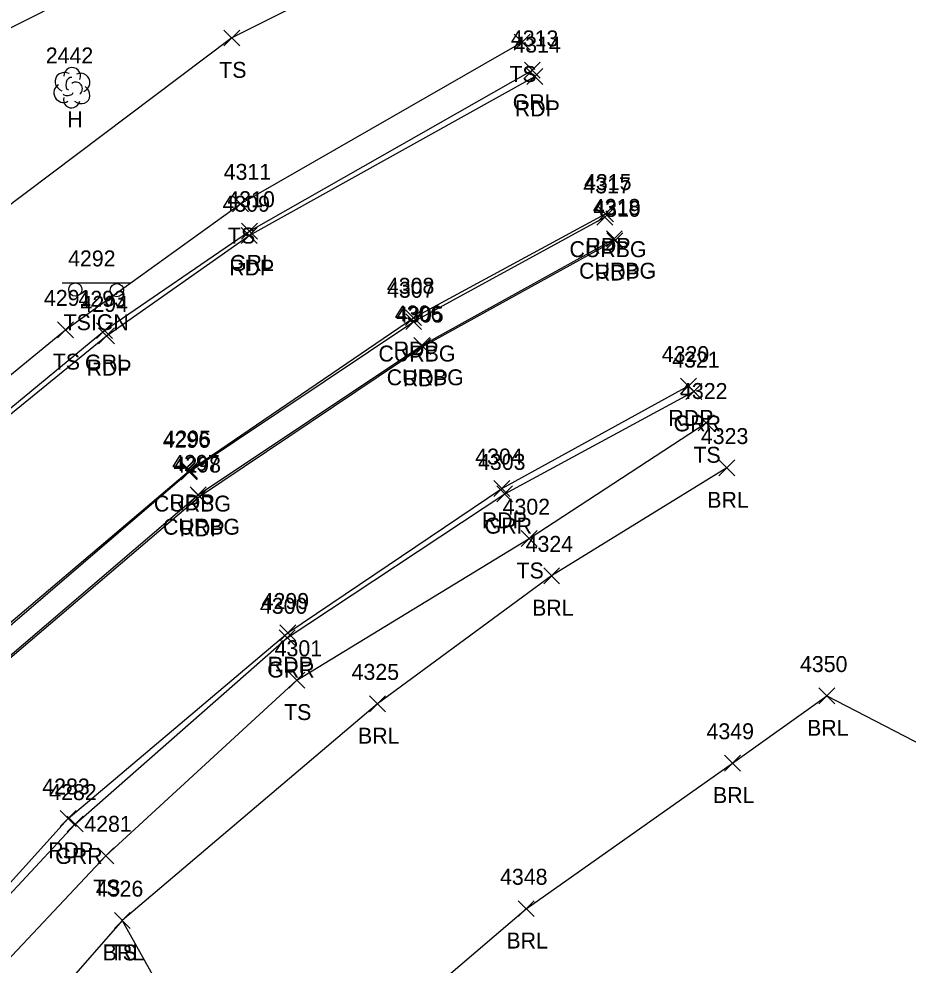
# Model space of a CAD drawing. Extents: x 1505656 to 1508446, y 700805 to 703031.
# Drawn here: x 1506963.6 to 1507075.1, y 702077.2 to 702195.8 of the extents above; entities that cross this region are included whole.
import ezdxf

# ---------------------------------------------------------------- set-up
doc = ezdxf.new("R2010")
doc.units = 0
for name, color, linetype in [('L_A', 7, 'Continuous'), ('L_I', 7, 'Continuous'), ('L_TIC', 7, 'Continuous'), ('LABL', 7, 'Continuous'), ('LELB', 7, 'Continuous'), ('LFNC', 7, 'Continuous'), ('LTD', 7, 'Continuous'), ('P_A', 7, 'Continuous'), ('P_I', 7, 'Continuous'), ('P_TIC', 7, 'Continuous'), ('PET', 7, 'Continuous'), ('R_A', 7, 'Continuous'), ('R_I', 7, 'Continuous'), ('R_TIC', 7, 'Continuous'), ('RC', 7, 'Continuous'), ('RGR', 7, 'Continuous'), ('S_A', 7, 'Continuous'), ('S_I', 7, 'Continuous'), ('SSGN', 7, 'Continuous')]:
    doc.layers.add(name, color=color, linetype=linetype)

msp = doc.modelspace()

# ---------------------------------------------------------------- linework, layer by layer
at = {"layer": 'L_TIC'}
for points in [[(1506989.29, 702192.44), (1506991.29, 702194.44)], [(1506991.29, 702192.44), (1506989.29, 702194.44)], [(1507025.67, 702191.92), (1507027.67, 702193.92)], [(1507027.67, 702191.92), (1507025.67, 702193.92)], [(1506990.38, 702171.65), (1506992.38, 702173.65)], [(1506992.38, 702171.65), (1506990.38, 702173.65)], [(1506968.42, 702155.84), (1506970.42, 702157.84)], [(1506970.42, 702155.84), (1506968.42, 702157.84)], [(1507048.74, 702144.16), (1507050.74, 702146.16)], [(1507050.74, 702144.16), (1507048.74, 702146.16)], [(1507051.35, 702138.51), (1507053.35, 702140.51)], [(1507053.35, 702138.51), (1507051.35, 702140.51)], [(1507026.57, 702129.65), (1507028.57, 702131.65)], [(1507028.57, 702129.65), (1507026.57, 702131.65)], [(1507029.38, 702124.98), (1507031.38, 702126.98)], [(1507031.38, 702124.98), (1507029.38, 702126.98)], [(1506997.42, 702111.89), (1506999.42, 702113.89)], [(1506999.42, 702111.89), (1506997.42, 702113.89)], [(1507063.87, 702109.91), (1507065.87, 702111.91)], [(1507065.87, 702109.91), (1507063.87, 702111.91)], [(1507007.56, 702108.93), (1507009.56, 702110.93)], [(1507009.56, 702108.93), (1507007.56, 702110.93)], [(1507052.07, 702101.48), (1507054.07, 702103.48)], [(1507054.07, 702101.48), (1507052.07, 702103.48)], [(1506973.48, 702089.87), (1506975.48, 702091.87)], [(1506975.48, 702089.87), (1506973.48, 702091.87)], [(1507026.17, 702083.23), (1507028.17, 702085.23)], [(1507028.17, 702083.23), (1507026.17, 702085.23)], [(1506975.55, 702081.74), (1506977.55, 702083.74)], [(1506977.55, 702081.74), (1506975.55, 702083.74)], [(1506975.55, 702081.74), (1506977.55, 702083.74)], [(1506977.55, 702081.74), (1506975.55, 702083.74)]]:
    msp.add_lwpolyline(points, dxfattribs=at)
at = {"layer": 'LABL'}
msp.add_lwpolyline([(1507052.35, 702139.51), (1507030.38, 702125.98), (1507008.56, 702109.93), (1506976.55, 702082.74), (1506991.06, 702056.7), (1507008.55, 702068.3), (1507027.17, 702084.23), (1507053.07, 702102.48), (1507064.87, 702110.91), (1507096.41, 702094.62), (1507120.62, 702079.29), (1507138.79, 702060.47), (1507154.26, 702038.91)], dxfattribs=at)
at = {"layer": 'LELB'}
for points in [[(1507023.62, 702210.14), (1506990.29, 702193.44), (1506954.68, 702166.67), (1506927.59, 702146.34), (1506906.08, 702127.14), (1506885.36, 702102.51), (1506869.7, 702082.79)], [(1506632.76, 701888.83), (1506647.51, 701883.24), (1506664.72, 701876.76), (1506685.76, 701867.06), (1506699.66, 701861.88), (1506724.17, 701854.86), (1506747, 701850.37), (1506762.18, 701847.23), (1506778.65, 701848.42), (1506793.74, 701856.34), (1506806.43, 701868.9), (1506814.02, 701881.67), (1506823.01, 701905.7), (1506834.94, 701947.87), (1506844.08, 701981.1), (1506857.42, 702015.82), (1506870, 702042.27), (1506893.48, 702079.96), (1506912.42, 702104.16), (1506937.96, 702131.04), (1506969.42, 702156.84), (1506991.38, 702172.65), (1507026.67, 702192.92)], [(1507070.39, 701756.85), (1507062.65, 701766.74), (1507035.94, 701785.73), (1507003.46, 701807.55), (1506985.45, 701821.27), (1506969.99, 701833.47), (1506956.98, 701845.36), (1506943.57, 701863.34), (1506931.46, 701884.5), (1506922.5, 701904.87), (1506918.24, 701922.45), (1506914.46, 701946.57), (1506916.38, 701967.92), (1506918.34, 701992.98), (1506925.22, 702017.51), (1506939.88, 702047.41), (1506952.89, 702067.91), (1506974.48, 702090.87), (1506998.42, 702112.89), (1507027.57, 702130.65), (1507049.74, 702145.16)], [(1506976.55, 702082.74), (1506962.58, 702066.78), (1506948.82, 702048.86), (1506937.32, 702030.62), (1506928.97, 702011.44), (1506924.75, 701991.39), (1506922.05, 701967.9), (1506922.32, 701944.51), (1506926.8, 701921.46), (1506932.43, 701898.62), (1506943.35, 701875.33), (1506959.66, 701854.04), (1506977.72, 701835.42), (1506996.18, 701821.09), (1507009.54, 701810.69), (1507022.62, 701801.64), (1507057.71, 701775.1), (1507073.71, 701768.8)]]:
    msp.add_lwpolyline(points, dxfattribs=at)
at = {"layer": 'LFNC'}
msp.add_lwpolyline([(1507015.48, 702220.45), (1507000.25, 702213.6), (1506981.11, 702204.06), (1506942.05, 702184.41), (1506930.7, 702179.18), (1506921.92, 702174.7), (1506891.87, 702159.82), (1506879.46, 702153.87), (1506851.82, 702140.45), (1506812.22, 702121.39), (1506786.34, 702109.48), (1506772.09, 702127.54), (1506754.61, 702149.98)], dxfattribs=at)
at = {"layer": 'LTD'}
msp.add_line((1506970.21, 702187.25), (1506970.21, 702187.25), dxfattribs=at)
msp.add_line((1506970.21, 702187.25), (1506970.21, 702187.25), dxfattribs=at)
msp.add_arc((1506970.25, 702188.68), 1.05, 335.5272, 180.9563, dxfattribs=at)
for centre, major_axis, ratio, start_param, end_param in [((1506969.41, 702187.91), (1.21, -0.51), 0.895232, 1.570796, 4.712389), ((1506971.25, 702187.83), (-1.14, -0.48), 0.949671, 1.570796, 4.712389), ((1506970, 702187.71), (-0.208, -0.792), 0.645439, 3.141593, 6.283185), ((1506970.71, 702187.08), (-0.5, 0.667), 0.989748, 3.141593, 6.283185), ((1506969.12, 702186.54), (0.58, -1.04), 0.959034, 3.141593, 6.283185), ((1506971.21, 702186.42), (-1.09, 0.79), 0.841452, 1.570796, 4.712389), ((1506970.21, 702185.75), (0.26, 1.06), 0.942809, 1.570796, 4.712389), ((1506969.75, 702186.5), (-0.625, -0.083), 0.423636, 0, 3.141593)]:
    msp.add_ellipse(centre, major_axis=major_axis, ratio=ratio, start_param=start_param, end_param=end_param, dxfattribs=at)
at = {"layer": 'P_TIC'}
for points in [[(1507027.27, 702187.61), (1507029.27, 702189.61)], [(1507029.27, 702187.61), (1507027.27, 702189.61)], [(1507036.14, 702170.37), (1507038.14, 702172.37)], [(1507038.14, 702170.37), (1507036.14, 702172.37)], [(1506991.45, 702167.65), (1506993.45, 702169.65)], [(1506993.45, 702167.65), (1506991.45, 702169.65)], [(1507037.31, 702167.02), (1507039.31, 702169.02)], [(1507039.31, 702167.02), (1507037.31, 702169.02)], [(1507012.06, 702157.36), (1507014.06, 702159.36)], [(1507014.06, 702157.36), (1507012.06, 702159.36)], [(1506973.57, 702155.09), (1506975.57, 702157.09)], [(1506975.57, 702155.09), (1506973.57, 702157.09)], [(1507013.23, 702153.75), (1507015.23, 702155.75)], [(1507015.23, 702153.75), (1507013.23, 702155.75)], [(1507046.53, 702148.79), (1507048.53, 702150.79)], [(1507048.53, 702148.79), (1507046.53, 702150.79)], [(1506983.97, 702138.19), (1506985.97, 702140.19)], [(1506985.97, 702138.19), (1506983.97, 702140.19)], [(1506985.23, 702134.93), (1506987.23, 702136.93)], [(1506987.23, 702134.93), (1506985.23, 702136.93)], [(1507023.14, 702135.94), (1507025.14, 702137.94)], [(1507025.14, 702135.94), (1507023.14, 702137.94)], [(1506996.29, 702117.82), (1506998.29, 702119.82)], [(1506998.29, 702117.82), (1506996.29, 702119.82)], [(1506968.77, 702094.55), (1506970.77, 702096.55)], [(1506970.77, 702094.55), (1506968.77, 702096.55)]]:
    msp.add_lwpolyline(points, dxfattribs=at)
at = {"layer": 'PET'}
for points in [[(1506825.47, 701904.58), (1506837.26, 701947.09), (1506847.69, 701980.14), (1506860.09, 702013.65), (1506873.31, 702039.3), (1506897.29, 702078.32), (1506916.09, 702102.48), (1506940.28, 702128.16), (1506974.57, 702156.09), (1506992.45, 702168.65), (1507028.27, 702188.61)], [(1506833.9, 701849.28), (1506832.93, 701848.28), (1506830.81, 701848.24), (1506830.36, 701850.51), (1506836.36, 701870.2), (1506844.2, 701897.55), (1506856.11, 701938.7), (1506866.3, 701972.92), (1506878.09, 702004.98), (1506890.93, 702030.34), (1506912.21, 702064.51), (1506931.15, 702089.05), (1506953.69, 702112.67), (1506984.97, 702139.19), (1507013.06, 702158.36), (1507037.14, 702171.37)], [(1506833.9, 701849.28), (1506839.36, 701868.92), (1506850.51, 701895.81), (1506859.71, 701938.03), (1506869.86, 701972.33), (1506881.61, 702003.37), (1506894.2, 702028.85), (1506914.39, 702061.94), (1506933.77, 702086.76), (1506956.19, 702110.33), (1506986.23, 702135.93), (1507014.23, 702154.75), (1507038.31, 702168.02)], [(1506912.11, 701920.69), (1506908.75, 701945.66), (1506907.98, 701968.56), (1506911.35, 701994), (1506918.79, 702020.39), (1506933.79, 702051.52), (1506948.37, 702071.85), (1506969.77, 702095.55), (1506997.29, 702118.82), (1507024.14, 702136.94), (1507047.53, 702149.79)]]:
    msp.add_lwpolyline(points, dxfattribs=at)
at = {"layer": 'R_TIC'}
for points in [[(1507026.96, 702188.39), (1507028.96, 702190.39)], [(1507028.96, 702188.39), (1507026.96, 702190.39)], [(1507036.04, 702169.95), (1507038.04, 702171.95)], [(1507038.04, 702169.95), (1507036.04, 702171.95)], [(1506991.5, 702168.22), (1506993.5, 702170.22)], [(1506993.5, 702168.22), (1506991.5, 702170.22)], [(1507037.24, 702167.25), (1507039.24, 702169.25)], [(1507039.24, 702167.25), (1507037.24, 702169.25)], [(1507012.08, 702156.86), (1507014.08, 702158.86)], [(1507014.08, 702156.86), (1507012.08, 702158.86)], [(1506973.31, 702155.73), (1506975.31, 702157.73)], [(1506975.31, 702155.73), (1506973.31, 702157.73)], [(1507013.11, 702153.88), (1507015.11, 702155.88)], [(1507015.11, 702153.88), (1507013.11, 702155.88)], [(1507047.19, 702148.1), (1507049.19, 702150.1)], [(1507049.19, 702148.1), (1507047.19, 702150.1)], [(1506983.93, 702138.04), (1506985.93, 702140.04)], [(1506985.93, 702138.04), (1506983.93, 702140.04)], [(1506985.06, 702135.14), (1506987.06, 702137.14)], [(1506987.06, 702135.14), (1506985.06, 702137.14)], [(1507023.49, 702135.27), (1507025.49, 702137.27)], [(1507025.49, 702135.27), (1507023.49, 702137.27)], [(1506996.23, 702117.22), (1506998.23, 702119.22)], [(1506998.23, 702117.22), (1506996.23, 702119.22)], [(1506969.65, 702093.85), (1506971.65, 702095.85)], [(1506971.65, 702093.85), (1506969.65, 702095.85)]]:
    msp.add_lwpolyline(points, dxfattribs=at)
at = {"layer": 'RC'}
for points in [[(1506833.59, 701849.62), (1506832.75, 701848.85), (1506831.11, 701849.18), (1506830.87, 701850.53), (1506836.46, 701870.07), (1506844.55, 701897.59), (1506856.47, 701938.61), (1506866.59, 701972.8), (1506878.5, 702004.68), (1506891.29, 702030.33), (1506912.36, 702064.19), (1506931.39, 702088.83), (1506953.86, 702112.39), (1506984.93, 702139.04), (1507013.08, 702157.86), (1507037.04, 702170.95)], [(1506833.59, 701849.62), (1506839.16, 701868.97), (1506850.08, 701895.94), (1506859.54, 701938.01), (1506869.53, 701972.37), (1506881.22, 702003.54), (1506893.86, 702028.96), (1506914.24, 702062.04), (1506933.53, 702086.9), (1506956.03, 702110.5), (1506986.06, 702136.14), (1507014.11, 702154.88), (1507038.24, 702168.25)]]:
    msp.add_lwpolyline(points, dxfattribs=at)
at = {"layer": 'RGR'}
for points in [[(1506824.88, 701904.65), (1506837.1, 701947.18), (1506847.09, 701980.47), (1506860.04, 702013.99), (1506872.77, 702039.69), (1506896.9, 702078.64), (1506915.2, 702102.02), (1506939.99, 702128.44), (1506974.31, 702156.73), (1506992.5, 702169.22), (1507027.96, 702189.39)], [(1506913.3, 701921.19), (1506910.1, 701945.77), (1506909.59, 701968.49), (1506912.98, 701994.07), (1506919.79, 702019.95), (1506934.62, 702051.22), (1506948.89, 702071.48), (1506970.65, 702094.85), (1506997.23, 702118.22), (1507024.49, 702136.27), (1507048.19, 702149.1)]]:
    msp.add_lwpolyline(points, dxfattribs=at)
at = {"layer": 'SSGN'}
for p, q in [((1506969, 702162.71), (1506977.59, 702162.71)), ((1506973.02, 702161.8), (1506973.02, 702161.8))]:
    msp.add_line(p, q, dxfattribs=at)
for centre in [(1506970.66, 702161.88), (1506975.87, 702161.81)]:
    msp.add_circle(centre, 0.833, dxfattribs=at)

# ---------------------------------------------------------------- texts
at = {"layer": 'L_A'}
for s, p in [('TS', (1506988.7, 702188.44)), ('TS', (1507025.08, 702187.92)), ('H', (1506969.64, 702182.25)), ('TS', (1506989.79, 702167.65)), ('TS', (1506967.83, 702151.84)), ('TS', (1507048.15, 702140.16)), ('BRL', (1507049.89, 702134.51)), ('TS', (1507025.98, 702125.65)), ('BRL', (1507027.93, 702120.98)), ('TS', (1506996.83, 702107.89)), ('BRL', (1507062.41, 702105.91)), ('BRL', (1507006.1, 702104.93)), ('BRL', (1507050.61, 702097.48)), ('TS', (1506972.89, 702085.87)), ('BRL', (1507024.71, 702079.23)), ('BRL', (1506974.09, 702077.74)), ('TS', (1506974.96, 702077.74))]:
    msp.add_text(s, height=2, dxfattribs=at).set_placement(p)
at = {"layer": 'L_I'}
for s, p in [('2442', (1506966.95, 702190.25)), ('4311', (1506989.26, 702175.65)), ('4291', (1506966.72, 702159.84)), ('4322', (1507046.48, 702148.16)), ('4323', (1507049.09, 702142.51)), ('4302', (1507024.23, 702133.65)), ('4324', (1507027.12, 702128.98)), ('4301', (1506995.65, 702115.89)), ('4350', (1507061.52, 702113.91)), ('4325', (1507005.3, 702112.93)), ('4349', (1507049.8, 702105.48)), ('4281', (1506971.78, 702093.87)), ('4348', (1507023.91, 702087.23)), ('4326', (1506973.23, 702085.74)), ('4326', (1506973.23, 702085.74))]:
    msp.add_text(s, height=2, dxfattribs=at).set_placement(p)
at = {"layer": 'P_A'}
for p in [(1507025.76, 702183.61), (1507034.62, 702166.37), (1506989.94, 702163.65), (1507035.79, 702163.02), (1507010.55, 702153.36), (1506972.06, 702151.09), (1507011.72, 702149.75), (1507045.02, 702144.79), (1506982.46, 702134.19), (1507021.63, 702131.94), (1506983.72, 702130.93), (1506994.78, 702113.82), (1506967.26, 702090.55)]:
    msp.add_text('RDP', height=2, dxfattribs=at).set_placement(p)
at = {"layer": 'P_I'}
for s, p in [('4314', (1507025.58, 702191.61)), ('4315', (1507034.44, 702174.37)), ('4309', (1506989.11, 702171.65)), ('4319', (1507035.61, 702171.02)), ('4308', (1507009.72, 702161.36)), ('4294', (1506971.31, 702159.09)), ('4305', (1507010.89, 702157.75)), ('4320', (1507044.18, 702152.79)), ('4295', (1506981.71, 702142.19)), ('4304', (1507020.8, 702139.94)), ('4298', (1506982.97, 702138.93)), ('4299', (1506994.02, 702121.82)), ('4283', (1506966.51, 702098.55))]:
    msp.add_text(s, height=2, dxfattribs=at).set_placement(p)
at = {"layer": 'R_A'}
for s, p in [('GRL', (1507025.5, 702184.39)), ('CURBG', (1507032.62, 702165.95)), ('GRL', (1506990.04, 702164.22)), ('CURBG', (1507033.82, 702163.25)), ('CURBG', (1507008.66, 702152.86)), ('GRL', (1506971.86, 702151.73)), ('CURBG', (1507009.7, 702149.88)), ('GRR', (1507045.67, 702144.1)), ('CURBG', (1506980.51, 702134.04)), ('GRR', (1507021.98, 702131.27)), ('CURBG', (1506981.65, 702131.14)), ('GRR', (1506994.72, 702113.22)), ('GRR', (1506968.13, 702089.85))]:
    msp.add_text(s, height=2, dxfattribs=at).set_placement(p)
at = {"layer": 'R_I'}
for s, p in [('4313', (1507025.27, 702192.39)), ('4317', (1507034.35, 702173.95)), ('4310', (1506989.72, 702172.22)), ('4318', (1507035.55, 702171.25)), ('4293', (1506971.05, 702159.73)), ('4307', (1507009.74, 702160.86)), ('4306', (1507010.72, 702157.88)), ('4321', (1507045.49, 702152.1)), ('4296', (1506981.61, 702142.04)), ('4297', (1506982.8, 702139.14)), ('4303', (1507021.15, 702139.27)), ('4300', (1506993.8, 702121.22)), ('4282', (1506967.39, 702097.85))]:
    msp.add_text(s, height=2, dxfattribs=at).set_placement(p)
at = {"layer": 'S_A'}
msp.add_text('TSIGN', height=2, dxfattribs=at).set_placement((1506969.19, 702156.79))
at = {"layer": 'S_I'}
msp.add_text('4292', height=2, dxfattribs=at).set_placement((1506969.75, 702164.79))

doc.saveas('drawing.dxf')
